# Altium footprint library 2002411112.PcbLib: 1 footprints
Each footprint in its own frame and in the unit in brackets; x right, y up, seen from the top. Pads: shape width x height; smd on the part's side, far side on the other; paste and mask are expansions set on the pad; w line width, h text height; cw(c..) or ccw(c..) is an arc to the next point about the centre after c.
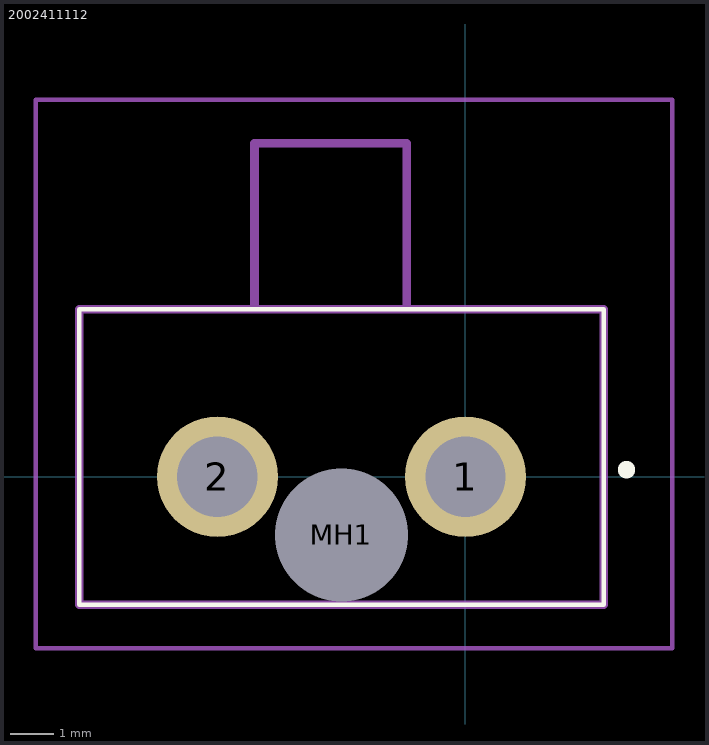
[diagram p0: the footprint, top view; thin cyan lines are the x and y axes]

## 2002411112 [mm]
pads (3):
  round 2.775 hole 1.85: 1(0,0) 2(-5.7,0)
  round 1.525 hole 3.05 unplated: MH1(-2.85,-1.34)
Top Overlay:
  lines w0.1: -8.875,-2.94 3.175,-2.94 3.175,3.85 -8.875,3.85 -8.875,-2.94
  lines w0.3: 3.65,0.16 3.65,0.16 ; 3.65,0.16 ccw(c3.7,0.16) 3.75,0.16 ; 3.65,0.16 cw(c3.7,0.16) 3.75,0.16 ; 3.75,0.16 3.75,0.16
Mechanical 15:
  lines w0.2: -4.85,3.85 -4.85,7.66 -1.35,7.66 -1.35,3.85 ; -8.875,-2.94 3.175,-2.94 3.175,3.85 -8.875,3.85 -8.875,-2.94
Mechanical 20:
  lines w0.1: -9.875,-3.94 4.75,-3.94 4.75,8.66 -9.875,8.66 -9.875,-3.94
